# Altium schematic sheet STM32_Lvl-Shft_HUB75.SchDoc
size A; SheetNumber: 4; SheetTotal: 5
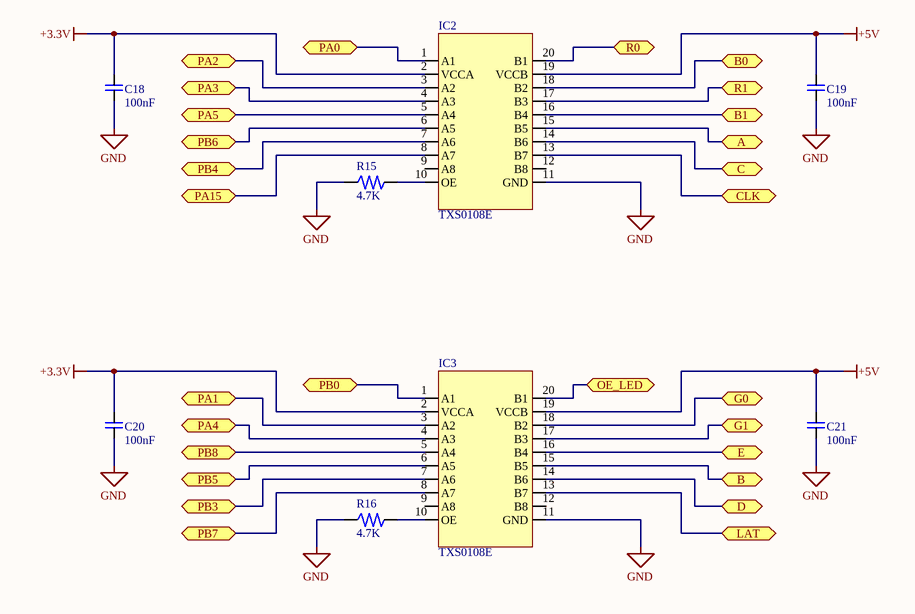
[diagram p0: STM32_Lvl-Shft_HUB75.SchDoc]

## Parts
C18  100nF  [SMT_CAP_MODEL_1206(3216)_SAMSUNG]
C19  100nF  [SMT_CAP_MODEL_1206(3216)_SAMSUNG]
C20  100nF  [SMT_CAP_MODEL_1206(3216)_SAMSUNG]
C21  100nF  [SMT_CAP_MODEL_1206(3216)_SAMSUNG]
IC2  TXS0108E  [SMT_TXS0108E_IC]
IC3  TXS0108E  [SMT_TXS0108E_IC]
R15  4.7K  [SMT_RES_MODEL_1206(3216)_ROHM]
R16  4.7K  [SMT_RES_MODEL_1206(3216)_ROHM]

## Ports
A (bidir), B0 (bidir), B1 (bidir), B (bidir), C (bidir), CLK (bidir), D (bidir), E (bidir), G0 (bidir), G1 (bidir), LAT (bidir), OE_LED (bidir), PA0 (bidir), PA1 (bidir), PA2 (bidir), PA3 (bidir), PA4 (bidir), PA5 (bidir), PA15 (bidir), PB0 (bidir), PB3 (bidir), PB4 (bidir), PB5 (bidir), PB6 (bidir), PB7 (bidir), PB8 (bidir), R0 (bidir), R1 (bidir)

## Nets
+3.3V: C18.1 C20.1 IC2.2(VCCA) IC3.2(VCCA)
+5V: C19.1 C21.1 IC2.19(VCCB) IC3.19(VCCB)
GND: C18.2 C19.2 C20.2 C21.2 IC2.11(GND) IC3.11(GND) R15.2 R16.2
A: IC2.15(B5) ; port A
B: IC3.15(B5) ; port B
B0: IC2.18(B2) ; port B0
B1: IC2.16(B4) ; port B1
C: IC2.14(B6) ; port C
CLK: IC2.13(B7) ; port CLK
D: IC3.14(B6) ; port D
E: IC3.16(B4) ; port E
G0: IC3.18(B2) ; port G0
G1: IC3.17(B3) ; port G1
LAT: IC3.13(B7) ; port LAT
OE_LED: IC3.20(B1) ; port OE_LED
PA0: IC2.1(A1) ; port PA0
PA1: IC3.3(A2) ; port PA1
PA2: IC2.3(A2) ; port PA2
PA3: IC2.4(A3) ; port PA3
PA4: IC3.4(A3) ; port PA4
PA5: IC2.5(A4) ; port PA5
PA15: IC2.8(A7) ; port PA15
PB0: IC3.1(A1) ; port PB0
PB3: IC3.7(A6) ; port PB3
PB4: IC2.7(A6) ; port PB4
PB5: IC3.6(A5) ; port PB5
PB6: IC2.6(A5) ; port PB6
PB7: IC3.8(A7) ; port PB7
PB8: IC3.5(A4) ; port PB8
R0: IC2.20(B1) ; port R0
R1: IC2.17(B3) ; port R1
NetIC2_10: IC2.10(OE) R15.1
NetIC3_10: IC3.10(OE) R16.1

Not connected (* = marked no-connect by the designer): IC2 9(A8) 12(B8); IC3 9(A8) 12(B8)

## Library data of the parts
C18-C21 = SMT_CAP_MODEL_1206(3216)_SAMSUNG: SMT Samsung Ceramic Capacitor MODEL *V *nF 1206(3216)  CL31B104KBCNNNC(etc.)
IC2 IC3 = SMT_TXS0108E_IC: TXS0108E 8-BIT Bi-Directional Level Shifter 1.2-3.6V(A) 1.65-5.5V(B)
R15 R16 = SMT_RES_MODEL_1206(3216)_ROHM: SMT ROHM Resistor MODEL 1206(3216) 1/4W MCR18ERTJ000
